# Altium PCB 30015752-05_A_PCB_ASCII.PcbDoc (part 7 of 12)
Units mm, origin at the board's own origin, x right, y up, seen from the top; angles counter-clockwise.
Board outline 100.05 x 72 mm, 10 copper layers (Top, GND_2, Signal_3, Signal_4, PWR_5, GND_6, Signal_7, Signal_8, GND_9, Bottom), stack 1.493 mm thick; 577 components, 546 nets, 2389 pads, 1412 vias.
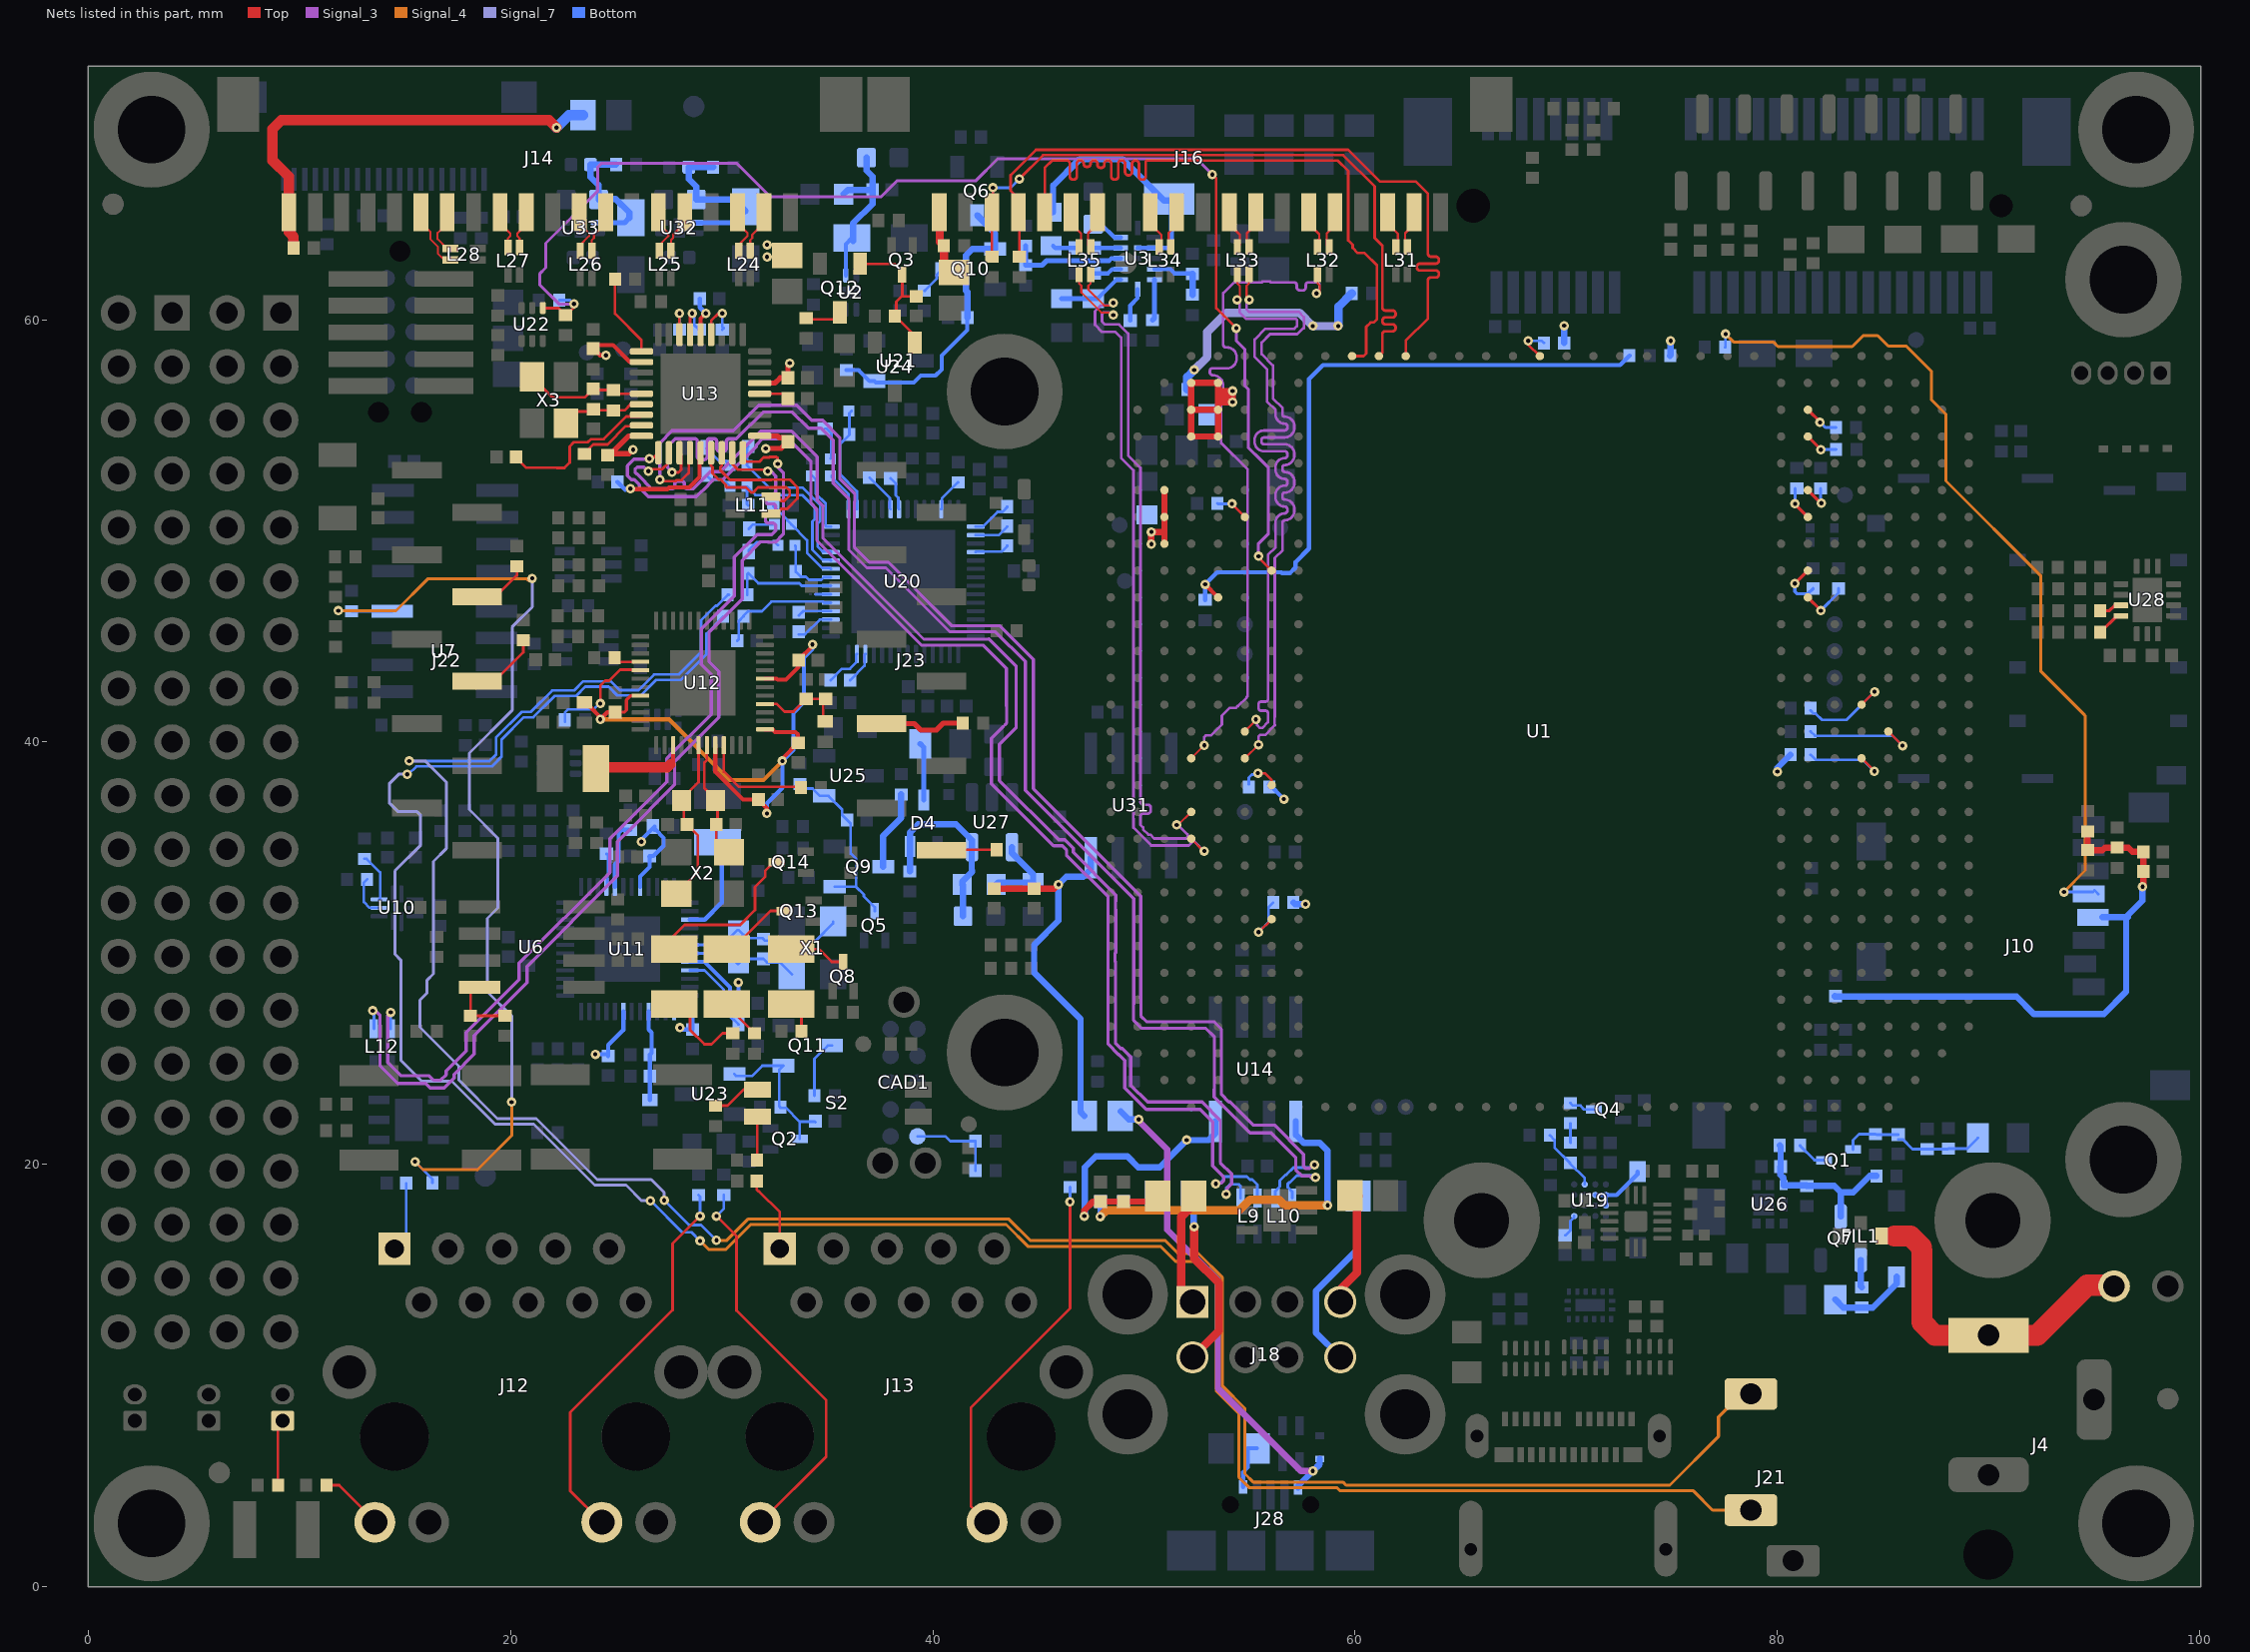
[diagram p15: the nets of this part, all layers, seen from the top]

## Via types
v1: diameter 0.45, hole 0.2, Top to Bottom, tented both sides, 1412 vias

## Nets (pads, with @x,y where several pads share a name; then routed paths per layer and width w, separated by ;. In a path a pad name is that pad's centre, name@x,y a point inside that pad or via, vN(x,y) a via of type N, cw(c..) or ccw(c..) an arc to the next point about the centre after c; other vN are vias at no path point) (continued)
MIPI_DSI1_DATA1_P: L32.4 U1.AK16 | length 32.8
  Top w0.102: U1.AK16@52.24,39.23 52.85,39.84 v1(52.86,39.84) ; v1(58.175,61.25) 58.311,61.25 58.335,61.273 58.335,61.614 58.225,61.724 L32.4@58.225,62.15
  Signal_3 w0.124: v1(52.86,39.84) 52.86,40.237 52.933,40.31 53.173,40.31 53.688,40.825 53.688,41.254 54.05,41.616 54.347,41.616 54.429,41.698 54.457,41.698 54.862,42.103 54.862,42.131 54.91,42.179 54.91,52.917 53.65,54.177 53.65,56.525 53.758,56.633 53.758,56.871 ccw(c53.25,56.871) 53.25,57.378 cw(c53.25,57.508) 53.121,57.508 53.121,57.573 cw(c53.25,57.573) 53.25,57.703 53.932,57.703 ccw(c53.932,58.163) 54.392,58.163 54.392,58.228 ccw(c53.932,58.228) 53.932,58.688 53.887,58.688 cw(c53.887,58.817) 53.758,58.817 53.758,61.258 54.267,61.767 55.581,61.767 55.628,61.814 55.972,61.814 56.019,61.767 57.111,61.767 cw(c57.111,61.64) 57.238,61.64 57.238,61.54 ccw(c57.383,61.54) 57.383,61.395 57.535,61.395 ccw(c57.535,61.522) 57.663,61.522 57.663,61.64 cw(c57.79,61.64) 57.79,61.767 58.244,61.767 58.317,61.694 58.317,61.48 58.175,61.338 v1(58.175,61.25)
MIPI_DSI1_DATA2_N: L33.1 U1.AH16 | length 33
  Top w0.102: U1.AH16@54.78,39.23 v1(55.425,39.875) ; L33.1@54.975,62.15 54.975,61.724 54.865,61.614 54.865,61.073 v1(54.989,60.95)
  Signal_3 w0.124: v1(54.989,60.95) 54.989,60.862 54.865,60.739 54.865,60.485 54.97,60.38 57.337,60.38 57.58,60.137 57.58,59.592 57.531,59.592 57.263,59.324 55.974,59.324 55.575,58.925 55.575,58.375 56.112,57.838 56.112,56.278 56.566,55.825 56.566,55.511 ccw(c56.664,55.511) 56.664,55.413 cw(c56.664,54.953) 57.124,54.953 57.124,54.888 cw(c56.664,54.888) 56.664,54.428 55.695,54.428 ccw(c55.695,54.298) 55.566,54.298 55.566,54.233 ccw(c55.695,54.233) 55.695,54.103 56.664,54.103 cw(c56.664,53.644) 57.124,53.644 57.124,53.578 cw(c56.664,53.578) 56.664,53.119 ccw(c56.664,53.02) 56.566,53.02 56.566,52.892 ccw(c56.664,52.892) 56.664,52.794 cw(c56.664,52.334) 57.124,52.334 57.124,52.269 cw(c56.664,52.269) 56.664,51.809 ccw(c56.664,51.711) 56.566,51.711 56.566,51.583 ccw(c56.664,51.583) 56.664,51.485 cw(c56.664,51.025) 57.124,51.025 57.124,50.96 cw(c56.664,50.96) 56.664,50.5 ccw(c56.664,50.402) 56.566,50.402 56.566,49.08 56.2,48.714 56.2,41.186 56.186,41.172 56.186,40.828 56.2,40.814 56.2,40.798 55.738,40.336 55.498,40.336 55.425,40.263 v1(55.425,39.875)
MIPI_DSI1_DATA2_P: L33.4 U1.AH15 | length 33
  Top w0.102: v1(54.411,60.95) 54.535,61.073 54.535,61.614 54.425,61.724 L33.4@54.425,62.15 ; U1.AH15@54.78,40.5 55.3,41.02 v1(55.3,41.075)
  Signal_3 w0.124: v1(54.411,60.95) 54.411,60.862 54.535,60.739 54.535,60.348 54.833,60.05 57.2,60.05 57.25,60 57.25,59.7 57.125,59.575 55.758,59.575 55.245,59.062 55.245,58.238 55.825,57.658 55.825,56.125 56.235,55.715 56.235,55.511 ccw(c56.664,55.511) 56.664,55.083 cw(c56.664,54.953) 56.793,54.953 56.793,54.888 cw(c56.664,54.888) 56.664,54.758 55.695,54.758 ccw(c55.695,54.298) 55.235,54.298 55.235,54.233 ccw(c55.695,54.233) 55.695,53.773 56.664,53.773 cw(c56.664,53.644) 56.793,53.644 56.793,53.578 cw(c56.664,53.578) 56.664,53.449 ccw(c56.664,53.02) 56.235,53.02 56.235,52.892 ccw(c56.664,52.892) 56.664,52.464 cw(c56.664,52.334) 56.793,52.334 56.793,52.269 cw(c56.664,52.269) 56.664,52.139 ccw(c56.664,51.711) 56.235,51.711 56.235,51.583 ccw(c56.664,51.583) 56.664,51.155 cw(c56.664,51.025) 56.793,51.025 56.793,50.96 cw(c56.664,50.96) 56.664,50.83 ccw(c56.664,50.402) 56.235,50.402 56.235,49.216 55.878,48.859 55.878,42.039 cw(c55.75,42.039) 55.75,41.912 55.552,41.912 ccw(c55.552,41.784) 55.424,41.784 55.424,41.615 ccw(c55.552,41.615) 55.552,41.487 55.75,41.487 cw(c55.75,41.36) 55.878,41.36 55.878,41.275 55.878,40.943 55.601,40.666 55.498,40.666 55.362,40.802 55.362,41.013 v1(55.3,41.075)
MIPI_DSI1_DATA3_N: L35.1 U1.AK19 | length 33.8
  Top w0.102: L35.1@47.475,62.15 47.475,61.724 47.365,61.614 47.365,61.425 48.115,60.675 48.427,60.675 v1(48.55,60.798) ; U1.AK19@52.24,35.42 52.84,34.82 52.85,34.81 52.86,34.82 v1(52.86,34.84)
  Signal_3 w0.124: v1(48.55,60.798) 48.462,60.798 48.339,60.675 47.951,60.675 47.684,60.409 47.684,59.766 48.025,59.425 48.65,59.425 48.92,59.155 48.92,53.455 49.504,52.871 49.504,37.275 49.498,37.268 49.498,37.165 49.495,37.165 49.495,37.127 49.501,37.121 49.501,37.084 49.504,37.08 49.504,37.043 49.504,36.608 49.504,36.571 49.501,36.567 49.501,36.53 49.495,36.524 49.495,36.486 49.498,36.486 49.498,36.383 49.504,36.376 49.504,35.945 50.347,35.102 52.131,35.102 52.3,35.272 52.403,35.272 52.847,34.827 52.85,34.825 52.86,34.835 v1(52.86,34.84)
MIPI_DSI1_DATA3_P: L35.4 U1.AK18 | length 33.9
  Top w0.102: L35.4@46.925,62.15 46.925,61.724 47.035,61.614 47.035,61.288 47.978,60.345 48.427,60.345 v1(48.55,60.221) ; v1(51.553,36.077) 51.627,36.077 U1.AK18@52.24,36.69
  Signal_3 w0.124: v1(48.55,60.221) 48.462,60.221 48.339,60.345 48.088,60.345 48.015,60.272 48.015,59.91 48.15,59.775 48.825,59.775 49.25,59.35 49.25,53.575 49.834,52.991 49.834,37.25 49.834,37.165 ccw(c49.962,37.165) 49.962,37.038 50.185,37.038 cw(c50.185,36.91) 50.312,36.91 50.312,36.741 cw(c50.185,36.741) 50.185,36.613 49.962,36.613 ccw(c49.962,36.486) 49.834,36.486 49.834,36.45 49.834,36.082 49.963,35.953 49.963,35.855 50.206,35.613 50.303,35.613 50.484,35.432 51.994,35.432 52.067,35.505 52.067,35.633 51.62,36.08 51.617,36.077 v1(51.553,36.077)
MIPI_DSI1_I2C0_SCL: J16.17 R182.1 U1.AB1 | length 35.9
  Top w0.127: R182.1@44.1,62.98 44.1,65.05 J16.17@44.05,65.1 44.05,65.75 43.684,66.116 43.684,66.847 44.886,68.048 59.676,68.048 61.175,66.55 62.869,66.55 63.45,65.969 63.45,63.15 63.45,63.134 ccw(c63.597,63.134) 63.597,62.987 63.825,62.987 cw(c63.825,62.839) 63.972,62.839 63.972,62.807 cw(c63.825,62.807) 63.825,62.66 63.45,62.66 63.075,62.66 ccw(c63.075,62.512) 62.928,62.512 62.928,62.48 ccw(c63.075,62.48) 63.075,62.333 63.45,62.333 63.825,62.333 cw(c63.825,62.185) 63.972,62.185 63.972,62.153 cw(c63.825,62.153) 63.825,62.006 63.597,62.006 ccw(c63.597,61.858) 63.45,61.858 63.45,61.8 63.45,60.055 62.4,59.005 U1.AB1@62.4,58.28
MIPI_DSI1_I2C0_SDA: J16.18 R181.1 U1.AC1 | length 32.9
  Top w0.127: R181.1@42.8,62.98 J16.18@42.8,65.1 42.852,65.152 v1(42.852,66.253) ; v1(44.1,66.675) 45.22,67.794 59.443,67.794 60.925,66.313 60.925,63.875 61.295,63.505 61.295,60.6 61.295,60.584 ccw(c61.442,60.584) 61.442,60.437 61.774,60.437 cw(c61.774,60.289) 61.921,60.289 61.921,60.257 cw(c61.774,60.257) 61.774,60.11 61.442,60.11 ccw(c61.442,59.962) 61.295,59.962 61.295,59.93 ccw(c61.442,59.93) 61.442,59.783 61.774,59.783 cw(c61.774,59.635) 61.921,59.635 61.921,59.603 cw(c61.774,59.603) 61.774,59.456 61.43,59.456 ccw(c61.43,59.32) 61.295,59.32 61.295,58.46 ; U1.AC1@61.13,58.28 61.295,58.445
  Bottom w0.127: v1(42.852,66.253) 43.678,66.253 v1(44.1,66.675)
MIPI_DSI1_IRQ_N: R253.2 R254.1 U1.AG9 U22.4 | length 62.6
  Top w0.127: U22.4@21.525,60.555 22.275,60.555 R254.1@22.6,60.23 22.655,60.23 23,60.575 v1(23,60.75) ; v1(53.24,66.88) 53.425,66.695 53.425,60.55 v1(54.375,59.6) ; v1(55.428,48.802) 55.428,48.742 U1.AG9@56.05,48.12
  Signal_3 w0.142: v1(23,60.75) 22.291,60.75 21.375,61.666 21.375,62.171 21.667,62.463 21.667,63.631 24.117,66.081 24.117,67.225 24.292,67.4 30.725,67.4 32.3,65.825 37.55,65.825 38.298,66.573 42.023,66.573 43.075,67.625 52.495,67.625 v1(53.24,66.88) ; v1(54.375,59.6) 54.375,59 54.775,58.6 54.775,56.875 54.95,56.7 54.95,53.93 55.271,53.61 55.29,53.61 55.9,53 55.9,49.872 55.428,49.399 v1(55.428,48.802)
  Bottom w0.127: R253.2@22.305,60.925 22.825,60.925 v1(23,60.75)
MIPI_DSI1_PWM0_OUT: J16.16 U1.AD1 | length 33.8
  Top w0.127: J16.16@45.3,65.1 45.3,67.2 45.641,67.54 46,67.54 46.163,67.54 46.343,67.54 cw(c46.343,67.393) 46.49,67.393 46.49,66.788 ccw(c46.638,66.788) 46.638,66.64 46.67,66.64 ccw(c46.67,66.788) 46.817,66.788 46.817,67.393 cw(c46.965,67.393) 46.965,67.54 46.997,67.54 cw(c46.997,67.393) 47.144,67.393 47.144,67.39 ccw(c47.292,67.39) 47.292,67.243 47.324,67.243 ccw(c47.324,67.39) 47.471,67.39 47.471,67.393 cw(c47.619,67.393) 47.619,67.54 47.651,67.54 cw(c47.651,67.393) 47.798,67.393 47.798,67.344 ccw(c47.946,67.344) 47.946,67.197 47.978,67.197 ccw(c47.978,67.344) 48.125,67.344 48.125,67.393 cw(c48.273,67.393) 48.273,67.54 48.305,67.54 cw(c48.305,67.393) 48.452,67.393 48.452,66.788 ccw(c48.6,66.788) 48.6,66.64 48.632,66.64 ccw(c48.632,66.788) 48.779,66.788 48.779,67.393 cw(c48.927,67.393) 48.927,67.54 48.959,67.54 cw(c48.959,67.393) 49.106,67.393 49.106,66.991 ccw(c49.254,66.991) 49.254,66.844 49.286,66.844 ccw(c49.286,66.991) 49.433,66.991 49.433,67.393 cw(c49.581,67.393) 49.581,67.54 49.613,67.54 cw(c49.613,67.393) 49.76,67.393 49.76,66.788 ccw(c49.908,66.788) 49.908,66.64 49.94,66.64 ccw(c49.94,66.788) 50.087,66.788 50.087,67.479 cw(c50.149,67.479) 50.149,67.54 59.18,67.54 59.675,67.045 59.675,63.762 59.887,63.55 59.887,63.406 60.131,63.163 60.45,63.163 61.041,62.572 61.041,60.028 60.886,59.874 60.734,59.874 60.525,59.665 60.525,58.405 60.4,58.28 U1.AD1@59.86,58.28
NetC5_2: C5.2 D4.2 R26.2 R28.1 U27.5 | length 9
  Bottom w0.3: R28.1@38.91,33.879 38.919,33.888 D4.2@38.919,35.059 38.919,35.719 39.3,36.1 41.1,36.1 41.85,35.35 U27.5@41.85,35.02 41.843,35.013 41.843,33.928 41.85,33.921 41.85,33.85 41.4,33.4 R26.2@41.4,33.25 41.43,33.22 C5.2@41.43,31.75
NetC7_1: C7.1 C8.2 C9.2 R41.1 U2.1 | length 7.8
  Bottom w0.2: U2.1@35.875,62.1 35.875,63.575 C7.1@36.175,63.875
  Bottom w0.3: R41.1@35.775,65.95 35.975,66.15 C9.2@37.14,66.15 ; C7.1@36.225,63.725 36.225,64.575 37.14,65.49 C9.2@37.14,66.15 ; C8.2@36.855,67.675 36.855,67.07 37.14,66.785 C9.2@37.14,66.15
NetC13_1: C13.1 U3.10 | length 1.2
  Bottom w0.2: C13.1@47.66,63.4 U3.10@48.9,63.4
NetC13_2: C13.2 R48.1 | length 1.1
  Bottom w0.2: R48.1@45.7,63.5 45.8,63.4 C13.2@46.74,63.4
NetC14_1: C14.1 U3.8 | length 1.3
  Bottom w0.2: C14.1@47.66,62.2 48.3,62.2 48.5,62.4 U3.8@48.9,62.4
NetC27_2: C27.2 C28.2 J10.4 R53.2 R54.1 R55.2 R56.1 R57.1 | length 26.5
  Top w0.3: R55.2@94.7,35.77 R53.2@94.7,34.88 95.398,34.88 95.518,35 R57.1@96.1,35 96.625,35 96.825,34.8 C28.2@97.34,34.8 C27.2@97.34,33.875 97.34,33.19 v1(97.3,33.15)
  Bottom w0.3: R54.1@82.725,27.97 82.725,27.948 91.327,27.948 92.15,27.125 95.467,27.125 96.525,28.183 96.525,31.625 96.6,31.7 96.519,31.7 ; J10.4@95.4,31.7 96.519,31.7 ; v1(97.3,33.15) 97.3,32.481 96.519,31.7
NetC34_1: C34.1 C112.1 U20.39 | length 7.9
  Bottom w0.127: C112.1@31.26,54 31.2,53.94 C34.1@31.2,53.1 32.247,52.053 33.819,52.053 34.67,51.202 34.67,50.47 34.549,50.35 34.549,49.25 34.763,49.036 35.133,49.036 U20.39@35.17,49
NetC34_2: C34.2 L18.2 | length 1.5
  Bottom w0.127: L18.2@29.305,53.95 29.305,53.885 29.893,53.296 30.204,53.296 C34.2@30.4,53.1
NetC35_1: C35.1 C113.1 U20.38 | length 7.7
  Bottom w0.127: C113.1@31.26,51.2 31.2,51.26 C35.1@31.2,52.1 31.599,51.7 33.812,51.7 34.416,51.097 34.416,50.575 34.295,50.455 34.295,49.104 34.763,48.636 35.133,48.636 U20.38@35.17,48.6
NetC35_2: C35.2 L19.2 | length 1.4
  Bottom w0.127: L19.2@29.305,52.675 29.305,52.61 29.536,52.379 29.574,52.379 29.616,52.421 30.079,52.421 C35.2@30.4,52.1
NetC36_1: C36.1 C114.1 U20.37 | length 4.3
  Bottom w0.127: C114.1@32.44,51.2 32.44,51.19 33.103,50.527 33.103,50.497 C36.1@33.3,50.3 34.041,49.559 34.041,48.958 34.763,48.236 35.133,48.236 U20.37@35.17,48.2
NetC36_2: C36.2 L20.2 | length 1.3
  Bottom w0.127: L20.2@31.28,50.1 31.48,50.3 C36.2@32.5,50.3
NetC41_1: C41.1 Q2.D Q11.G R70.2 U23.G | length 7.4
  Bottom w0.127: U23.G@30.6,24.275 30.691,24.184 31.434,24.184 31.925,24.675 Q11.G@32.925,24.675 32.73,24.48 32.73,22.75 R70.2@32.78,22.7 32.78,22.675 33.04,22.675 33.69,22.025 ; Q2.D@33.69,21.2 33.69,22.025 ; C41.1@34.44,22 34.415,22.025 33.69,22.025
NetC42_2: C42.2 R102.1 U11.7 X1.3 | length 5.4
  Bottom w0.127: U11.7@28.49,29.992 30.258,29.992 30.75,29.5 R102.1@30.8,29.5 31.035,29.735 C42.2@31.975,29.735 32.148,29.562 32.764,29.562 X1.3@33.325,29
NetC43_2: C43.2 R102.2 U11.6 X1.1 | length 7.7
  Bottom w0.127: U11.6@28.49,30.392 30.042,30.392 30.75,31.1 R102.2@30.8,31.1 31.186,30.714 31.926,30.714 C43.2@31.975,30.665 32.043,30.597 34.459,30.597 35.275,31.413 X1.1@35.275,31.5
NetC45_2: C45.2 J12.1 | length 3.3
  Bottom w0.127: J12.1@14.501,16.005 15.06,16.564 C45.2@15.06,19.107
NetC49_2: C49.2 C50.2 L2.2 U11.16 | length 4.3
  Bottom w0.2: U11.16@26.54,27.242 26.54,26.385 26.68,26.245 26.68,25.273 C50.2@26.6,25.192 C49.2@26.6,24.167 L2.2@26.6,23.055
NetC56_2: C56.2 C57.2 C58.2 C59.2 L4.1 U11.8 U11.13 U11.19 U11.44 | length 14.1
  Bottom w0.2: v1(24.01,25.21) 24.55,25.21 C57.2@24.625,25.135 24.625,25.65 25.34,26.365 U11.19@25.34,27.242 ; U11.44@26.14,33.142 26.14,33.64 26.585,34.085 C59.2@26.585,34.5 ; v1(26.2,35.275) 26.2,35.38 26.82,36 26.82,35.85 26.864,35.85 27.252,35.462 27.252,35.088 26.764,34.6 C59.2@26.585,34.6 ; C59.2@26.56,34.575 C59.2@26.61,34.525 ; U11.13@27.74,27.242 28.283,27.242 28.625,26.9 C58.2@28.625,26.385 28.115,26.385 v1(28.025,26.475) ; U11.8@28.49,29.592 29.189,29.592 30.391,28.391 30.391,28.009 30.775,27.625 C56.2@30.79,27.625 v1(30.79,28.615)
NetC60_2: C60.2 R103.1 U12.7 X2.3 | length 5.7
  Top w0.127: U12.7@29.3,39.85 29.3,39.15 29.175,39.025 29.175,37.825 29.8,37.2 29.8,36.16 C60.2@29.74,36.1 29.74,35.385 X2.3@30.35,34.775
NetC61_2: C61.2 R103.2 U12.6 X2.1 | length 8
  Top w0.127: X2.1@27.85,32.825 28.875,33.85 28.875,35.585 C61.2@28.36,36.1 28.2,36.26 28.2,37.4 28.9,38.1 U12.6@28.9,39.85
NetC63_2: C63.2 J13.1 | length 3.7
  Top w0.127: C63.2@31.66,19.2 31.66,18.8 31.745,18.715 31.772,18.715 32.751,17.737 J13.1@32.751,16.005
NetC67_2: C67.2 C68.2 L5.2 U12.16 | length 4.2
  Top w0.127: U12.16@32.05,41.8 32.612,41.8 32.968,41.444 33.407,41.444 34,42.037 C68.2@34,42.04 34.8,42.04 34.8,41.08 L5.2@34.7,40.98
NetC74_2: C74.2 C75.2 C76.2 C77.2 L7.1 U12.8 U12.13 U12.19 U12.44 | length 34.1
  Top w0.15: C77.2@24.95,41.415 25.39,41.415 25.487,41.512 25.487,41.987 25.7,42.2 U12.44@26.15,42.2
  Top w0.2: L7.1@23.5,41.88 23.645,41.88 23.773,41.752 23.773,41.663 24.25,41.186 v1(24.25,41.075) 24.59,41.415 C77.2@24.95,41.415 ; U12.8@29.7,39.85 29.7,38.589 31.014,37.275 C74.2@31.74,37.275 32.133,36.882 32.133,36.627 v1(32.14,36.62) ; U12.13@32.05,40.6 32.4,40.6 32.527,40.473 32.734,40.473 32.738,40.477 33.498,40.477 33.614,40.361 C76.2@33.614,39.96 ; U12.19@32.05,43 32.598,43 32.65,42.948 33.037,42.948 33.64,43.551 C75.2@33.64,43.875 33.64,43.886 34.3,44.546 v1(34.3,44.625) ; v1(32.875,39.1) 32.875,39.221 C76.2@33.614,39.96 ; C76.2@33.625,39.96 C76.2@33.614,39.96
  Signal_4 w0.2: v1(24.25,41.075) 27.503,41.075 30.378,38.2 31.975,38.2 v1(32.875,39.1)
  Bottom w0.2: v1(32.14,36.62) 32.14,37.1 32.875,37.835 v1(32.875,39.1) 33.4,39.625 33.4,41.398 33.412,41.398 33.9,41.886 33.9,44.009 34.3,44.409 v1(34.3,44.625)
NetC79_1: C79.1 C115.1 U20.36 | length 3.1
  Bottom w0.127: C79.1@33.475,49.3 33.51,49.265 C115.1@33.51,48.075 33.51,48.065 33.746,47.828 33.984,47.828 34.128,47.684 34.725,47.684 34.84,47.8 U20.36@35.17,47.8
NetC79_2: C79.2 L21.2 | length 1.7
  Bottom w0.127: L21.2@31.28,49.025 31.28,49.09 31.658,49.468 32.532,49.468 C79.2@32.675,49.325
NetC81_1: C81.1 R135.1 U13.32 X3.3 | length 5.7
  Top w0.127: X3.3@21.019,57.291 21.985,56.325 23.513,56.325 C81.1@23.919,56.731 23.979,56.671 R135.1@24.869,56.671 R135.1@25.04,56.5 ; R135.1@25.14,56.5 U13.32@26.2,56.5
NetC82_1: C82.1 R135.2 U13.33 X3.1 | length 4
  Top w0.127: X3.1@22.619,55.091 23.179,55.651 23.919,55.651 23.979,55.711 R135.2@24.869,55.711 25.411,55.711 25.7,56 U13.33@26.2,56
NetC85_2: C85.2 C86.2 L29.2 U14.5 | length 19.8
  Signal_4 w0.4: v1(47.925,17.525) 48.225,17.825 54.527,17.825 55.027,18.325 56.4,18.325 56.665,18.06 v1(58.7,18.06)
  Bottom w0.3: v1(47.925,17.525) 47.95,17.55 C85.2@47.95,18.24 C86.2@49.025,18.24 50.39,18.24 L29.2@50.65,18.5 ; U14.5@57.195,22.03 57.195,21.399 57.569,21.025 58.325,21.025 58.7,20.65 v1(58.7,18.06)
NetC87_2: C87.2 C88.2 L30.2 U14.8 | length 14.3
  Top w0.3: v1(47.175,17.55) 47.175,17.825 47.59,18.24 C87.2@47.95,18.24 C88.2@49.025,18.24 50.65,18.24 L30.2@50.65,18.5
  Bottom w0.3: v1(47.175,17.55) 47.2,17.575 47.2,19.856 47.721,20.377 49.221,20.377 49.732,19.866 50.741,19.866 v1(52.025,21.15) 53.075,21.15 53.385,21.46 U14.8@53.385,22.03
NetC89_1: C89.1 Q3.D Q12.G R145.2 U24.G | length 6.9
  Top w0.127: Q12.G@36.55,62.65 38.175,62.65 38.55,62.275 Q3.D@38.55,62.135 38.55,61.135 38.525,61.11 ; U24.G@39.225,59 U24.G@39.15,58.925 39.15,59.242 38.217,60.175 R145.2@38.205,60.175 38.271,60.241 38.271,60.855 38.525,61.11 ; C89.1@39.225,61.11 38.525,61.11
NetC90_2: C90.2 C91.2 C92.2 C93.2 C94.2 C95.2 L15.1 U13.5 U13.10 U13.15 U13.23 U13.29 U13.36 | length 18.8
  Top w0.2: v1(24.52,58.32) 24.23,58.32 C94.2@23.919,58.631 24.088,58.8 24.764,58.8 24.765,58.799 24.851,58.799 25.65,58 U13.29@26.2,58 ; v1(25.676,52.003) 25.657,52.003 25.627,51.973 27.423,51.973 27.514,52.064 28.464,52.064 28.95,52.55 28.95,53.65 U13.5@29,53.7 ; U13.23@29,59.3 29,60.05 v1(29.25,60.3)
  Top w0.25: C90.2@24.6,53.66 C90.2@24.76,53.66 ; v1(25.8,53.85) 25.61,53.66 C90.2@24.76,53.66 ; U13.36@26.2,54.5 25.6,54.5 C90.2@24.76,53.66 ; U13.10@31.8,54.5 32.641,54.5 32.731,54.41 32.955,54.41 C92.2@33.14,54.225 32.815,53.9 v1(32.08,53.9) ; U13.15@31.8,57 32.525,57 32.775,57.25 C93.2@33.14,57.25 33.14,57.865 v1(33.22,57.945)
  Bottom w0.2: C91.2@25.06,52.325 25.433,51.952 25.484,52.003 v1(25.676,52.003) ; C95.2@28.965,61 28.965,60.585 v1(29.25,60.3)
  other v1: 32.15,62.975 32.15,63.55
NetC96_2: C96.2 U13.14 | length 1.4
  Top w0.127: U13.14@31.8,56.5 32.915,56.5 C96.2@33.14,56.275
NetC97_2: C97.2 U13.34 | length 7.7
  Top w0.127: C97.2@20.26,53.5 20.26,53.472 20.74,52.992 22.195,52.992 22.203,52.984 22.547,52.984 22.8,53.237 22.8,54 23,54.2 23.661,54.2 23.81,54.35 24.412,54.35 25.483,55.421 26.121,55.421 U13.34@26.2,55.5
NetC108_2: C108.2 U19.D4 | length 1.1
  Bottom w0.127: C108.2@69.95,16.635 69.96,16.635 70.196,16.871 70.196,17.32 70.38,17.503 U19.D4@70.38,17.55
NetC109_1: C109.1 R159.2 U20.44 | length 5.2
  Bottom w0.127: C109.1@36.15,55.675 36.045,55.57 R159.2@36.045,54.575 36.045,54.55 35.609,54.114 35.609,52.667 36.4,51.876 U20.44@36.4,51.03
NetC110_1: C110.1 U20.42 | length 2.9
  Bottom w0.127: C110.1@34.3,52.6 34.446,52.454 34.446,51.785 34.924,51.308 34.924,50.236 34.96,50.2 U20.42@35.17,50.2
NetC111_1: C111.1 U20.43 | length 1.9
  Bottom w0.127: C111.1@35.2,52.6 35.2,52.55 36,51.75 U20.43@36,51.03
NetC111_2: C111.2 L17.2 | length 1.6
  Bottom w0.127: L17.2@34.9,54.845 34.965,54.845 35.196,54.614 35.196,53.465 C111.2@35.165,53.435
NetC116_1: C116.1 R164.1 U20.35 | length 5.2
  Bottom w0.127: R164.1@31.205,46.975 31.205,47.945 C116.1@31.26,48 31.26,47.99 31.735,47.516 33.672,47.516 33.788,47.4 U20.35@35.17,47.4
NetC117_1: C117.1 R165.1 U20.33 | length 5.7
  Bottom w0.127: C117.1@30.74,44.8 30.809,44.868 30.809,45.729 R165.1@31.03,45.95 31.03,45.975 31.251,46.196 31.899,46.196 32.353,46.65 34.789,46.65 34.84,46.6 U20.33@35.17,46.6
NetC127_1: C127.1 U20.27 | length 2
  Bottom w0.127: C127.1@35.165,42.925 35.165,42.935 35.697,43.467 36.068,43.467 36.363,43.763 36.363,44.133 U20.27@36.4,44.17
NetC127_2: C127.2 U20.26 | length 1.5
  Bottom w0.127: C127.2@36.085,42.925 36.085,42.935 36.764,43.613 36.764,44.133 U20.26@36.8,44.17
NetC128_2: C128.2 U20.32 | length 1.6
  Bottom w0.127: C128.2@33.66,46 33.86,46.2 U20.32@35.17,46.2
NetC129_2: C129.2 U20.31 | length 1.8
  Bottom w0.127: C129.2@33.66,45.1 33.95,45.1 34.65,45.8 U20.31@35.17,45.8
NetC130_1: C130.1 U20.48 | length 1.9
  Bottom w0.127: C130.1@37,52.515 37.01,52.515 37.964,51.561 37.964,51.066 U20.48@38,51.03
NetC131_2: C131.2 U20.49 | length 1.6
  Bottom w0.127: C131.2@38,52.49 38.01,52.49 38.246,52.254 38.246,51.691 38.363,51.574 38.363,51.066 U20.49@38.4,51.03
NetC132_2: C132.2 Q1.G R25.2 R64.1 R162.1 R255.1 | length 6.8
  Bottom w0.127: Q1.G@83.59,20.7 83.59,21.14 83.88,21.43 R25.2@84.65,21.43 ; R25.2@84.695,21.41 C132.2@85.725,21.41 ; C132.2@85.725,21.185 85.94,21.185 86.405,20.72 R64.1@87.1,20.72 88.075,20.72 R162.1@88.1,20.745 88.995,20.745 R255.1@89.5,21.25
NetC133_1: C133.1 Q6.D Q10.G R193.2 U21.G | length 14.4
  Bottom w0.2: R193.2@35.9,57.62 36.48,57.62 37,57.1 U21.G@37.225,57.1 37.302,57.023 39.098,57.023 39.427,57.352 40.127,57.352 40.423,57.648 40.423,58.298 41.635,59.51 C133.1@41.635,60.1
  Bottom w0.3: C133.1@41.635,60.1 41.635,61.315 41.575,61.375 41.575,63.05 41.875,63.35 Q10.G@42.95,63.35 42.95,64.1 Q6.D@42.1,64.95
NetC134_1: C134.1 Q5.D Q9.G R169.2 U25.G | length 9
  Bottom w0.127: R169.2@33.7,38.02 33.921,37.799 34.301,37.799 34.65,37.45 U25.G@34.85,37.45 35.05,37.45 35.704,36.796 35.704,36.537 C134.1@35.94,36.3 36.109,36.131 36.109,34.727 36.36,34.476 36.36,33.15 ; Q9.G@35.35,33.15 36.36,33.15 ; Q5.D@37.25,31.99 37.25,32.175 36.737,32.688 36.737,32.773 36.36,33.15
NetC135_2: C135.2 U3.11 | length 1.6
  Bottom w0.2: C135.2@47.6,64.53 47.97,64.53 48.6,63.9 U3.11@48.9,63.9
NetC136_2: C136.2 U3.6 | length 1.6
  Bottom w0.2: C136.2@49.35,59.96 49.35,60.675 49.7,61.025 U3.6@49.7,61.45
NetC142_1: C142.1 Q7.3 R21.1 R23.1 R24.2 U26.3 | length 8
  Bottom w0.3: R23.1@80.12,20.9 80.16,20.86 C142.1@80.16,19.9 80.15,19.89 80.15,19.5 80.3,19.35 U26.3@80.3,19.01 81.37,19.01 R21.1@81.4,18.98 82.695,18.98 83,18.675 ; Q7.3@83,17.53 83,18.675 ; R24.2@84.695,19.45 84.375,19.45 83.6,18.675 83,18.675
NetC148_2: C148.2 C149.2 L37.2 U31.8 | length 17.9
  Top w0.3: C149.2@42.9,33.06 C148.2@44.8,33.06 45.76,33.06 v1(45.952,33.252)
  Bottom w0.3: v1(45.952,33.252) 45.952,31.536 44.798,30.381 44.798,29.077 47,26.875 47,22.475 L37.2@47.175,22.3 ; v1(45.952,33.252) 46.325,33.625 47.125,33.625 47.485,33.985 U31.8@47.485,34.53
NetC155_1: C155.1 C156.2 C157.2 R2.2 U32.1 | length 7.9
  Bottom w0.25: U32.1@28.81,64.6 30.575,64.6 C155.1@31.125,65.15
  Bottom w0.3: R2.2@29.595,67.225 C157.2@28.435,67.225 28.435,66.665 28.795,66.305 C156.2@28.795,65.7 30.575,65.7 C155.1@31.125,65.15
NetC159_1: C159.1 C160.2 C161.2 R3.2 U33.1 | length 6.5
  Bottom w0.25: U33.1@24.21,64.6 25.4,64.6 C159.1@25.625,64.825
  Bottom w0.3: R3.2@24.995,67.35 C161.2@23.785,67.35 23.785,66.765 24.17,66.38 C160.2@24.17,65.7 24.195,65.725 24.975,65.725 25.625,65.075 C159.1@25.625,64.825
NetCAD1_5: CAD1.5 R14.2 R29.2 | length 4.2
  Bottom w0.127: CAD1.5@39.27,21.33 40.595,21.33 40.825,21.1 R29.2@42.02,21.1 R14.2@42.02,19.7
NetD2_2: D2.2 J28.1 L37.1 | length 23.2
  Signal_3 w0.3: v1(49.75,22.125) 49.75,22.06 51.1,20.71 51.1,16.9 53.5,14.5 53.5,9.4 57.425,5.475 v1(58,5.475)
  Bottom w0.3: L37.1@48.9,22.5 49.275,22.125 v1(49.75,22.125) ; J28.1@57.3,4.7 57.3,4.775 v1(58,5.475) 58.325,5.8 D2.2@58.325,6.05
NetD3_K: D3.K R19.1 R20.1 | length 3.9
  Bottom w0.3: R19.1@82.75,13.6 83.13,13.22 R20.1@84,13.22 84.52,13.22 85.65,14.35 D3.K@85.65,14.675
NetD4_3: D4.3 R31.1 | length 2.7
  Bottom w0.25: R31.1@39.4,39.92 39.569,39.751 D4.3@39.569,37.259
NetD5_A: D5.A R42.1 | length 1.5
  Top w0.127: D5.A@33.3,27.6 33.78,27.12 R42.1@33.78,26.3
NetD5_K: D5.K Q8.D | length 2.7
  Top w0.127: D5.K@33.3,30.2 34.6,30.2 35.21,29.59 Q8.D@35.75,29.59
NetD8_A: D8.A U19.B1 U19.B2 U19.C1 | length 3
  Bottom w0.2: U19.B2@71.38,18.55 U19.B1@71.88,18.55 ; U19.C1@71.88,18.05 U19.B1@71.88,18.55 ; D8.A@73.38,19.65 73.38,19.541 72.389,18.55 U19.B1@71.88,18.55
NetD11_A: D11.A R203.1 | length 2
  Top w0.127: D11.A@30.1,27.6 30.155,27.6 R203.1@31.55,26.205
NetD11_K: D11.K Q13.D | length 3.6
  Top w0.127: D11.K@30.1,30.2 D11.K@30.25,30.2 30.52,30.2 32.32,32 Q13.D@32.97,32
NetD12_A: D12.A R204.1 | length 4.7
  Top w0.127: D12.A@27.6,27.6 D12.A@27.75,27.6 28.5,27.6 28.5,26.362 29.178,25.685 29.522,25.685 30.043,26.205 R204.1@30.525,26.205
NetD12_K: D12.K Q14.D | length 7.8
  Top w0.127: D12.K@27.6,30.2 27.6,30.7 28.24,31.34 30.88,31.34 31.58,32.04 31.58,33.14 32.06,33.62 32.06,33.9 32.46,34.3 Q14.D@32.61,34.3
NetFIL1_1: FIL1.1 J4.1 J5.1 | length 15.4
  Top w1: 85.55,16.6 86.3,16.6 86.823,16.077 86.823,15.951 86.85,15.924 86.85,12.525 87.471,11.904 J4.1@90,11.904 92.304,11.904 94.675,14.275 J5.1@95.955,14.275
NetJ6_1: J6.1 R18.2 | length 3.1
  Top w0.127: R18.2@8.98,4.8 8.98,7.63 J6.1@9.2,7.85
NetJ10_5: J10.5 R58.2 | length 41.4
  Signal_4 w0.142: v1(77.55,59.325) 77.925,58.95 79.812,58.95 80.029,58.733 83.55,58.733 84.068,59.251 84.754,59.251 85.255,58.75 86.11,58.75 87.292,57.568 87.292,56.224 87.989,55.527 87.989,52.37 92.469,47.89 92.469,43.365 94.544,41.29 94.59,41.245 94.59,33.915 v1(93.575,32.9)
  Bottom w0.127: R58.2@77.53,58.7 77.55,58.72 v1(77.55,59.325) ; v1(93.575,32.9) 94.95,32.9 95.025,32.975 J10.5@95.2,32.8
NetJ12_D1: J12.D1 R84.1 | length 3
  Top w0.127: R84.1@11.28,4.8 11.88,4.8 13.571,3.109 J12.D1@13.571,3.051
NetJ12_D3: J12.D3 R83.1 | length 18.7
  Top w0.127: J12.D3@24.305,3.051 22.825,4.531 22.825,8.25 27.675,13.1 27.675,16.25 v1(28.975,17.55)
  Bottom w0.127: R83.1@28.9,18.545 28.98,18.465 28.975,18.46 v1(28.975,17.55)
NetJ13_D1: J13.D1 R116.1 | length 19.1
  Top w0.127: v1(29.75,17.55) 30.7,16.6 30.7,13.075 34.95,8.825 34.95,6.165 J13.D1@31.836,3.051
  Bottom w0.127: v1(29.75,17.55) 30.1,17.9 R116.1@30.1,18.545
NetJ13_D3: J13.D3 R115.1 | length 18.1
  Top w0.127: J13.D3@42.571,3.051 42.555,3.051 41.8,3.806 41.8,8.475 46.5,13.175 v1(46.5,18.225)
  Bottom w0.127: v1(46.5,18.225) R115.1@46.5,18.92
NetJ14_2: J14.2 L24.2 | length 2.1
  Top w0.102: L24.2@31.35,63.275 31.35,63.775 31.45,63.875 31.45,64.025 32,64.575 J14.2@32,65.1
NetJ14_3: J14.3 L24.3 | length 2.2
  Top w0.102: J14.3@30.75,65.1 30.75,64.575 31.22,64.105 31.22,63.97 30.8,63.55 L24.3@30.8,63.275
NetJ14_5: J14.5 L25.2 | length 2.1
  Top w0.102: L25.2@27.6,63.275 27.6,63.775 27.7,63.875 27.7,64.025 28.25,64.575 J14.5@28.25,65.1
NetJ14_6: J14.6 L25.3 | length 2.2
  Top w0.102: J14.6@27,65.1 27,64.575 27.47,64.105 27.47,63.97 27.05,63.55 L25.3@27.05,63.275
NetJ14_8: J14.8 L26.2 | length 2.1
  Top w0.102: L26.2@23.85,63.275 23.85,63.775 23.95,63.875 23.95,64.025 24.5,64.575 J14.8@24.5,65.1
NetJ14_9: J14.9 L26.3 | length 2.2
  Top w0.102: J14.9@23.25,65.1 23.25,64.575 23.72,64.105 23.72,63.97 23.3,63.55 L26.3@23.3,63.275
NetJ14_11: J14.11 L27.2 | length 1.9
  Top w0.102: L27.2@20.425,63.425 20.425,63.851 20.315,63.961 20.315,64.09 20.75,64.525 J14.11@20.75,65.1
NetJ14_12: J14.12 L27.3 | length 1.9
  Top w0.102: J14.12@19.5,65.1 19.5,64.575 19.985,64.09 19.985,63.961 19.875,63.851 L27.3@19.875,63.425
NetJ14_14: J14.14 L28.2 | length 2.3
  Top w0.102: J14.14@17,65.1 17,64.575 16.54,64.115 16.54,63.822 16.987,63.375 L28.2@17.15,63.375
NetJ14_15: J14.15 L28.3 | length 3
  Top w0.102: J14.15@15.75,65.1 15.75,64.625 16.21,64.165 16.21,63.81 16.553,63.467 16.553,63.147 16.875,62.825 L28.3@17.15,62.825
NetJ14_20: J14.20 L8.2 R134.2 | length 21.3
  Top w0.5: R134.2@9.72,63.4 9.72,63.93 9.5,64.15 J14.20@9.5,65.1 9.5,66.775 8.725,67.55 8.725,69.025 9.15,69.45 21.825,69.45 v1(22.175,69.1)
  Bottom w0.5: v1(22.175,69.1) 22.775,69.7 L8.2@23.425,69.7
NetJ16_2: J16.2 L31.2 | length 1.9
  Top w0.102: L31.2@62.475,63.45 62.375,63.55 62.375,64.1 62.8,64.525 J16.2@62.8,65.1
NetJ16_3: J16.3 L31.3 | length 1.9
  Top w0.102: J16.3@61.55,65.1 61.55,64.55 62.025,64.075 62.025,63.55 L31.3@61.925,63.45
NetJ16_5: J16.5 L32.2 | length 1.9
  Top w0.102: L32.2@58.775,63.45 58.65,63.575 58.65,64.075 59.05,64.475 J16.5@59.05,65.1
NetJ16_6: J16.6 L32.3 | length 1.9
  Top w0.102: J16.6@57.8,65.1 57.8,64.55 58.3,64.05 58.3,63.825 58.225,63.75 L32.3@58.225,63.45
NetJ16_8: J16.8 L33.2 | length 1.9
  Top w0.102: L33.2@54.975,63.45 54.875,63.55 54.875,64.1 55.3,64.525 J16.8@55.3,65.1
NetJ16_9: J16.9 L33.3 | length 1.9
  Top w0.102: J16.9@54.05,65.1 54.05,64.525 54.545,64.03 54.545,63.57 L33.3@54.425,63.45
NetJ16_11: J16.11 L34.2 | length 1.8
  Top w0.102: L34.2@51.275,63.45 51.175,63.55 51.175,64.125 51.55,64.5 J16.11@51.55,65.1
NetJ16_12: J16.12 L34.3 | length 1.9
  Top w0.102: J16.12@50.3,65.1 50.3,64.556 50.825,64.031 50.825,63.55 L34.3@50.725,63.45
NetJ16_14: J16.14 L35.2 | length 1.9
  Top w0.102: L35.2@47.475,63.45 47.35,63.575 47.35,64.1 47.8,64.55 J16.14@47.8,65.1
NetJ16_15: J16.15 L35.3 | length 1.9
  Top w0.102: J16.15@46.55,65.1 46.55,64.55 47.02,64.08 47.02,63.795 46.925,63.7 L35.3@46.925,63.45
NetJ16_20: J16.20 L36.2 R215.2 | length 3.1
  Top w0.4: J16.20@40.3,65.1 40.327,65.073 40.327,63.693 R215.2@40.52,63.5 40.52,62.73 L36.2@41,62.25
NetJ18_A1: J18.A1 L30.1 | length 5.5
  Top w0.4: J18.A1@52.301,13.485 51.768,14.018 51.768,17.518 52.198,17.948 52.198,18.348 L30.1@52.35,18.5
NetJ18_A4: J18.A4 L14.2 | length 5.4
  Top w0.4: J18.A4@59.301,13.485 59.301,14.076 60.098,14.873 60.098,18.448 L14.2@60.15,18.5
NetJ18_B1: J18.B1 L29.1 | length 8.6
  Top w0.4: J18.B1@52.301,10.865 53.55,12.114 53.55,14.375 52.375,15.55 v1(52.375,17.05)
  Bottom w0.3: L29.1@52.35,18.5 52.35,17.075 v1(52.375,17.05)
NetJ18_B4: J18.B4 L13.2 | length 8.9
  Bottom w0.3: J18.B4@59.301,10.865 58.15,12.016 58.15,14.006 60.123,15.979 60.123,18.473 L13.2@60.15,18.5
NetJ21_2: J21.2 R165.2 | length 113.9
  Signal_4 w0.142: v1(28.975,16.375) 29.373,15.977 30.202,15.977 31.375,17.15 43.473,17.15 44.525,16.098 50.802,16.098 51.5,15.4 52.5,15.4 53.425,14.475 53.425,9.275 54.5,8.2 54.5,5.175 55,4.675 59.15,4.675 59.292,4.533 76.025,4.533 76.933,3.625 J21.2@78.75,3.625
  Signal_7 w0.142: v1(15.1,38.475) 14.7,38.475 14.275,38.05 14.275,37.1 14.675,36.7 15.576,36.7 15.738,36.538 15.738,35.113 14.528,33.903 14.528,29.951 14.802,29.677 14.802,24.927 15.789,23.94 17.225,23.94 19.265,21.9 21.101,21.9 23.988,19.013 25.471,19.013 26.21,18.275 ; v1(26.626,18.276) 26.211,18.276 ; 26.21,18.275 26.211,18.276
  Bottom w0.127: v1(15.1,38.475) 15.163,38.475 15.534,38.846 19.105,38.846 19.573,39.313 19.573,40.12 20.628,41.176 21.072,41.176 22.082,42.185 23.107,42.185 23.543,42.621 24.644,42.621 25.06,42.205 26.165,42.205 26.906,42.947 28.068,42.947 29.279,44.158 29.279,45.134 30.07,45.925 R165.2@30.07,45.95 ; v1(26.626,18.276) 28.119,16.783 28.566,16.783 v1(28.975,16.375)
NetJ21_3: J21.3 R164.2 | length 115.6
  Signal_4 w0.142: v1(29.75,16.4) 30.244,16.4 31.263,17.419 43.584,17.419 44.604,16.4 51,16.4 51.625,15.775 52.575,15.775 53.725,14.625 53.725,9.5 54.776,8.449 54.776,5.351 55.175,4.952 59.423,4.952 59.573,4.802 74.902,4.802 77.212,7.113 77.212,8.037 78.3,9.125 J21.3@78.75,9.125 ; J21.3@78.85,9.025 78.925,9.1 J21.3@79.4,9.1
  Signal_7 w0.142: v1(15.2,39.1) 15.956,39.1 16.949,38.107 16.949,34.95 16.349,34.35 16.349,29.024 16.049,28.724 16.049,28.126 15.702,27.779 15.702,26.496 17.549,24.649 17.549,23.997 19.376,22.169 21.213,22.169 24.099,19.283 26.667,19.283 27.275,18.675 v1(27.275,18.3)
  Bottom w0.127: v1(15.2,39.1) 19,39.1 19.319,39.419 19.319,40.225 20.523,41.43 20.967,41.43 21.977,42.439 23.002,42.439 23.438,42.875 24.749,42.875 25.165,42.459 26.059,42.459 26.801,43.201 27.963,43.201 29.025,44.263 29.025,45.77 29.706,46.45 29.771,46.45 30.295,46.975 R164.2@30.345,46.975 ; v1(27.275,18.3) 28.45,17.125 29.025,17.125 v1(29.75,16.4)
NetJ22_4: J22.4 R189.2 | length 2.7
  Top w0.127: J22.4@18.417,46.875 19.275,46.875 20.3,47.9 R189.2@20.3,48.32
NetJ22_6: J22.6 R190.2 | length 3.3
  Top w0.127: J22.6@18.417,42.875 19.225,42.875 20.6,44.25 R190.2@20.6,44.82
NetJ23_7: J23.7 R196.1 | length 4.1
  Top w0.25: J23.7@37.567,40.875 39.125,40.875 39.432,40.568 40.168,40.568 40.5,40.9 R196.1@41.42,40.9
NetJ23_10: J23.10 R197.1 | length 2.6
  Top w0.127: J23.10@40.417,34.875 40.442,34.9 R197.1@43.02,34.9
NetJ28_5: J28.5 L39.2 | length 2.3
  Bottom w0.2: J28.5@54.7,4.725 54.7,5.425 54.925,5.65 54.925,6.55 L39.2@55.35,6.55
NetL1_1: L1.1 R48.2 U3.2 U3.13 | length 11.9
  Bottom w0.2: U3.13@49.7,63.4 U3.2@50.5,63.4 51.2,63.4
  Bottom w0.25: 51.2,63.4 51.3,63.5 51.3,65.55 L1.1@51.2,65.65
  Bottom w0.3: R48.2@45.7,65.1 45.7,66.351 46.949,67.6 49,67.6 50.95,65.65 L1.1@51.2,65.65
NetL3_1: L3.1 U11.3 | length 4.8
  Bottom w0.2: U11.3@28.49,31.592 29.199,31.592 30,32.393 30,35.152 L3.1@30.14,35.292
NetL6_1: L6.1 U12.3 | length 4.4
  Top w0.2: 27.575,38.95 27.7,39.075 U12.3@27.7,39.85
  Top w0.5: L6.1@24.2,38.7 24.299,38.799 27.424,38.799 27.575,38.95
NetL9_1: L9.1 U13.1 | length 62.6
  Top w0.132: v1(26.575,53.425) 26.636,53.486 26.786,53.486 U13.1@27,53.7
  Signal_3 w0.142: 34.505,50.955 34.505,49.545 39.475,44.575 42.4,44.575 ; 43.312,40.712 43.491,40.891 43.491,41.7
  Signal_3 w0.157: v1(26.575,53.425) 26.516,53.425 26.481,53.39 26.478,53.393 25.847,53.393 25.532,53.078 25.532,52.622 25.721,52.433 25.855,52.433 26.107,52.181 26.107,52.047 26.528,51.626 28.806,51.626 29.357,52.177 29.357,52.184 29.614,52.44 30.084,52.44 31.649,54.005 31.649,54.078 31.93,54.359 33.152,54.359 34.228,53.283 34.228,51.306 34.505,51.029 34.505,50.955 ; 42.4,44.575 43.491,43.484 43.491,41.7 ; 43.312,40.712 42.775,40.175 42.775,38.025 45.718,35.082 46.14,35.082 46.333,34.89 46.333,34.642 48.3,32.675 48.3,25.689 48.784,25.205 48.804,25.205 49.093,24.916 49.093,23.626 50.116,22.603 52.656,22.603 53.252,22.007 53.252,19.927 53.782,19.397 53.782,19.228 53.683,19.129 53.458,19.129 v1(53.402,19.073)
  Bottom w0.132: v1(53.402,19.073) 53.577,19.073 53.75,19.246 53.75,19.375 53.793,19.418 54.878,19.418 55.012,19.284 55.139,19.284 55.375,19.048 L9.1@55.375,18.4
NetL9_4: L9.4 U13.2 | length 62.7
  Top w0.132: v1(26.525,52.825) 26.525,52.875 26.475,52.925 27.175,52.925 27.5,53.25 U13.2@27.5,53.7
  Signal_3 w0.142: 34.803,51.178 34.803,49.647 39.575,44.875 42.65,44.875
  Signal_3 w0.157: v1(26.525,52.825) 26.325,53.025 26,53.025 25.9,52.925 25.9,52.775 25.957,52.718 25.973,52.718 26.391,52.299 26.391,52.284 26.681,51.994 27.55,51.994 27.641,51.994 ccw(c27.641,52.132) 27.779,52.132 27.779,52.211 cw(c27.916,52.211) 27.916,52.349 28.099,52.349 cw(c28.099,52.211) 28.236,52.211 28.236,52.132 ccw(c28.373,52.132) 28.373,51.994 28.6,51.994 28.653,51.994 29.467,52.808 29.932,52.808 31.851,54.727 33.304,54.727 34.525,53.506 34.525,51.456 34.803,51.178 ; 42.65,44.875 43.95,43.575 43.95,40.7 43.15,39.9 43.15,38.175 45.958,35.367 46.258,35.367 46.647,34.978 46.647,34.781 48.668,32.76 48.668,32.467 48.649,32.448 48.649,32.092 48.668,32.073 48.668,30.017 48.629,29.978 48.629,29.622 48.649,29.602 48.649,25.742 48.902,25.489 48.975,25.489 49.377,25.087 49.377,24.8 49.377,23.744 50.172,22.949 52.757,22.949 53.62,22.086 53.62,20.08 54.15,19.55 54.15,19.075 53.944,18.869 53.944,18.643 v1(53.888,18.587)
  Bottom w0.132: v1(53.888,18.587) 53.888,18.863 54.075,19.05 54.5,19.05 54.575,18.975 L9.4@54.575,18.4
NetL10_1: L10.1 U13.3 | length 65.7
  Top w0.132: v1(27.65,52.775) 27.95,52.775 28.075,52.9 28.075,53.625 U13.3@28,53.7
  Signal_3 w0.142: 36.025,51.514 36.025,49.1 36.875,48.25 37.775,48.25 40.801,45.224 42.976,45.224 ; 49.511,27.6 49.511,26.814 49.875,26.45 52.925,26.45 53.325,26.05 53.325,23.555
  Signal_3 w0.157: v1(27.65,52.775) 27.65,52.798 27.434,53.014 27.434,54.009 27.798,54.373 28.275,54.373 28.712,54.373 cw(c28.712,54.236) 28.849,54.236 28.849,53.515 ccw(c28.986,53.515) 28.986,53.377 29.169,53.377 ccw(c29.169,53.515) 29.306,53.515 29.306,54.236 cw(c29.444,54.236) 29.444,54.373 29.627,54.373 cw(c29.627,54.236) 29.764,54.236 29.764,53.912 ccw(c29.901,53.912) 29.901,53.774 30.084,53.774 ccw(c30.084,53.912) 30.221,53.912 30.221,54.236 cw(c30.359,54.236) 30.359,54.373 30.45,54.373 30.701,54.373 31.959,55.631 33.348,55.631 34.11,54.869 34.7,54.869 35.278,54.291 35.278,52.261 36.025,51.514 ; 42.976,45.224 44.388,43.812 44.388,37.712 49.511,32.589 49.511,27.6 ; 53.325,23.555 53.325,23.187 55.021,21.491 56.029,21.491 57.191,20.329 57.191,19.751 57.492,19.45 57.836,19.45 57.996,19.291 58.084,19.379 58.125,19.379 v1(58.128,19.376)
  Bottom w0.132: L10.1@57.025,18.4 57.025,18.7 56.809,18.916 56.809,19.084 56.864,19.139 56.901,19.139 57.237,19.475 58.029,19.475 v1(58.128,19.376)
NetL10_4: L10.4 U13.4 | length 65.6
  Top w0.132: v1(27.075,52.425) 27.143,52.357 27.823,52.357 27.873,52.407 28.103,52.407 28.318,52.622 28.443,52.747 28.443,53.643 U13.4@28.5,53.7
  Signal_3 w0.142: 36.28,51.78 36.302,51.758 36.302,51.399 36.294,51.392 36.294,49.212 36.987,48.519 37.887,48.519 40.905,45.501 43.174,45.501 ; 49.848,27.875 49.848,27.027 50.125,26.75 53.325,26.75 53.668,26.407 53.668,23.733
  Signal_3 w0.157: v1(27.075,52.425) 27.066,52.434 27.066,54.162 27.645,54.741 30.549,54.741 31.754,55.947 33.553,55.947 34.263,55.237 34.779,55.237 35.594,54.422 35.594,52.466 36.28,51.78 ; 43.174,45.501 44.756,43.919 44.756,37.794 49.848,32.702 49.848,27.875 ; 53.668,23.733 53.668,23.303 54.022,22.949 54.083,22.949 55.174,21.859 56.182,21.859 57.559,20.482 57.559,19.903 57.644,19.818 57.836,19.818 57.996,19.978 v1(58.075,19.978)
  Bottom w0.132: L10.4@56.225,18.4 56.225,18.725 56.441,18.941 56.441,19.237 56.711,19.507 56.748,19.507 57.084,19.843 57.94,19.843 v1(58.075,19.978)
NetL11_1: L11.1 U13.6 | length 6.6
  Top w0.132: U13.6@29.5,53.7 29.5,53.084 29.566,53.018 29.566,52.722 29.865,52.423 29.961,52.423 30.206,52.178 30.206,52.082 30.232,52.057 31.15,52.057 31.382,51.825 31.493,51.825 31.725,52.057 33.072,52.057 33.225,51.904 33.225,51.684 32.95,51.409 32.841,51.409 32.625,51.625 L11.1@32.325,51.625
NetL11_4: L11.4 U13.7 | length 6.9
  Top w0.132: U13.7@30,53.7 30,53.084 29.934,53.018 29.934,52.875 30.4,52.41 32.35,52.41 32.365,52.425 33.225,52.425 33.593,52.057 33.593,51.532 33.103,51.041 32.816,51.041 32.6,50.825 L11.4@32.325,50.825
NetL12_1: L12.1 U13.8 | length 46.4
  Top w0.132: U13.8@30.5,53.7 30.5,53.175 30.775,52.9 32.2,52.9 32.175,52.875 32.177,52.873 v1(32.177,52.828)
  Signal_3 w0.157: v1(14.325,27.2) 14.184,27.059 14.184,24.816 14.8,24.2 16.131,24.2 16.342,23.989 16.698,23.989 16.951,24.242 16.951,24.422 17.9,25.371 17.9,26.25 20.407,28.757 20.407,29.528 24.7,33.821 24.7,35.421 27.4,38.121 27.4,39.221 29.5,41.321 29.5,43.2 29.032,43.668 29.032,45.353 30.6,46.921 30.6,48.752 31.673,49.825 32.375,49.825 32.556,50.006 32.556,50.175 32.556,50.229 ccw(c32.418,50.229) 32.418,50.366 32.212,50.366 cw(c32.212,50.504) 32.075,50.504 32.075,50.687 cw(c32.212,50.687) 32.212,50.824 32.418,50.824 ccw(c32.418,50.961) 32.556,50.961 32.556,51.144 ccw(c32.418,51.144) 32.418,51.281 32.212,51.281 cw(c32.212,51.419) 32.075,51.419 32.075,51.602 cw(c32.212,51.602) 32.212,51.739 32.418,51.739 ccw(c32.418,51.876) 32.556,51.876 32.556,52.196 32.556,52.425 32.556,52.603 32.34,52.819 32.181,52.819 32.177,52.823 v1(32.177,52.828)
  Bottom w0.132: L12.1@14.325,26.427 v1(14.325,27.2)
NetL12_4: L12.4 U13.9 | length 46.7
  Top w0.132: U13.9@31,53.7 31,53.475 31.2,53.275 31.775,53.275 31.982,53.482 32.253,53.482 32.271,53.5 32.6,53.5 32.65,53.45 v1(32.65,53.175)
  Signal_3 w0.157: v1(13.476,27.276) 13.599,27.276 13.816,27.059 13.816,24.663 14.647,23.832 15.978,23.832 16.189,23.621 16.851,23.621 17.319,24.089 17.319,24.269 18.268,25.218 18.268,26.097 20.775,28.604 20.775,29.375 25.068,33.668 25.068,35.278 25.423,35.632 25.432,35.632 27.768,37.968 27.768,39.068 29.868,41.168 29.868,43.353 29.4,43.821 29.4,45.2 30.968,46.768 30.968,48.603 31.848,49.483 32.205,49.483 32.231,49.457 32.528,49.457 32.924,49.853 32.924,52.756 32.706,52.974 32.706,53.119 v1(32.65,53.175)
  Bottom w0.132: v1@13.501,27.276 13.525,27.253 L12.4@13.525,26.427
NetNT1_1: NT1.1 U20.34 | length 0.7
  Bottom w0.127: NT1.1@34.452,47 U20.34@35.17,47
NetQ1_D: Q1.D R23.2 | length 1.4
  Bottom w0.127: R23.2@81.08,20.9 81.08,20.875 81.755,20.2 Q1.D@82.21,20.2
NetQ4_D: Q4.D R152.1 | length 1.2
  Bottom w0.127: R152.1@70.2,22.905 70.318,22.787 70.675,22.787 70.675,22.775 70.85,22.6 Q4.D@71.31,22.6
NetQ7_1: Q7.1 R20.2 | length 1.3
  Bottom w0.3: Q7.1@83.95,15.47 83.95,14.23 R20.2@84,14.18
NetQ9_D: Q9.D R166.1 | length 3.8
  Bottom w0.3: Q9.D@37.65,34.1 37.65,35.55 38.5,36.4 R166.1@38.5,37.52
NetQ10_D: Q10.D R167.1 | length 1.6
  Bottom w0.127: R167.1@39.6,61.38 39.625,61.38 40.188,61.943 40.188,62.138 40.45,62.4 Q10.D@40.65,62.4
NetQ11_D: Q11.D R160.1 | length 2.8
  Bottom w0.127: R160.1@34.395,23.25 34.395,24.995 35.025,25.625 Q11.D@35.225,25.625
NetQ12_D: Q12.D R161.1 | length 2
  Top w0.127: R161.1@34,60.08 34.068,60.012 35.6,60.012 Q12.D@35.6,60.35
NetR4_1: R4.1 R7.1 R8.1 R9.1 R231.2 R256.1 R257.2 | length 15.9
  Signal_7 w0.4: v1(52.38,57.62) 53,58.24 53,59.425 53.9,60.325 57.375,60.325 v1(58,59.7) v1(59.2,59.7)
  Bottom w0.2: R8.1@55.93,38 v1(56.63,37.3)
  Bottom w0.3: R9.1@57.08,32.4 57.155,32.325 v1(57.65,32.325) ; v1(69.9,59.72) 69.905,59.715 R4.1@69.905,58.9 ; R231.2@74.92,58.3 74.95,58.33 v1(74.95,59) ; v1(80,38.6) 80,38.78 R7.1@80.62,39.4
  Bottom w0.4: R256.1@52.055,56.7 52.055,57.295 v1(52.38,57.62) ; v1(59.2,59.7) 59.22,59.72 59.22,60.625 R257.2@59.845,61.25
NetR4_2: R4.2 U1.U1 | length 1.7
  Top w0.127: v1(68.2,59) 68.2,58.83 U1.U1@68.75,58.28
  Bottom w0.127: v1(68.2,59) 68.845,59 R4.2@68.945,58.9
NetR5_2: R5.2 U1.D15 | length 5.6
  Top w0.127: U1.D15@85.26,40.5 85.929,39.831 v1(85.929,39.827)
  Bottom w0.127: R5.2@81.58,40.5 81.784,40.296 85.455,40.296 85.923,39.827 v1(85.929,39.827)
NetR6_2: R6.2 U1.E14 | length 4.6
  Top w0.127: U1.E14@83.99,41.77 84.6,42.38 v1(84.61,42.38)
  Bottom w0.127: R6.2@81.58,41.5 81.726,41.354 81.821,41.354 82.125,41.05 83.28,41.05 v1(84.61,42.38)
NetR7_2: R7.2 U1.E16 | length 4.2
  Top w0.127: U1.E16@83.99,39.23 84.6,38.62 v1(84.6,38.61)
  Bottom w0.127: R7.2@81.58,39.4 81.826,39.154 84.057,39.154 v1(84.6,38.61)
NetR8_2: R8.2 U1.AG17 | length 1.9
  Top w0.127: v1(55.4,38.525) 55.725,38.525 56.05,38.2 U1.AG17@56.05,37.96
  Bottom w0.127: R8.2@54.97,38 54.97,38.32 55.113,38.463 55.338,38.463 v1(55.4,38.525)
NetR9_2: R9.2 U1.AG22 | length 2.6
  Top w0.127: v1(55.43,31) 55.44,31 U1.AG22@56.05,31.61
  Bottom w0.127: v1(55.43,31) 55.899,31.469 55.899,32.179 R9.2@56.12,32.4
NetR11_2: R11.2 R59.2 U6.8 | length 3.5
  Top w0.127: U6.8@18.62,28.295 U6.8@18.53,28.385 18.1,28.385 R11.2@18.1,27.04 R59.2@19.74,27.04
NetR26_1: R26.1 R27.2 U27.4 | length 3.9
  Bottom w0.3: R26.1@43,33.25 43.1,33.35 R27.2@44.75,33.35 44.75,33.75 43.75,34.75 U27.4@43.75,35.02
NetR34_1: R34.1 S2.4 | length 2.1
  Top w0.127: R34.1@31.68,20.2 31.69,20.21 S2.4@31.69,22.265
NetR35_1: R35.1 S2.3 | length 2.3
  Top w0.127: R35.1@29.7,22.78 30.28,22.78 31.035,23.535 S2.3@31.69,23.535
NetR43_1: R43.1 R44.2 U3.4 | length 2.9
  Bottom w0.2: U3.4@50.5,62.4 51.25,62.4 51.45,62.2 R43.1@52.27,62.2
  Bottom w0.25: R43.1@52.27,62.2 R43.1@52.3,62.17
  Bottom w0.3: R44.2@52.3,61.18 R43.1@52.3,62.17
NetR45_2: R45.2 R47.1 U3.9 | length 5.5
  Bottom w0.2: 48.348,62.798 48.45,62.9 U3.9@48.9,62.9
  Bottom w0.25: R45.2@44.4,63.495 R47.1@44.4,62.58 45.18,62.58 45.398,62.798 48.348,62.798
NetR46_2: R46.2 U3.5 | length 2
  Bottom w0.25: R46.2@50.4,59.98 50.5,60.08 U3.5@50.5,61.9
NetR49_1: R49.1 R50.2 U3.7 | length 3.2
  Bottom w0.2: R50.2@47.8,61 48.7,61.9 U3.7@48.9,61.9
  Bottom w0.25: R49.1@46.1,61 R50.2@47.6,61 R50.2@47.8,61
NetR61_2: R61.2 R233.2 U7.8 | length 48
  Signal_4 w0.142: v1(11.84,46.22) 14.57,46.22 16.073,47.723 20.775,47.723 20.827,47.671 20.946,47.671 v1(21.025,47.75) ; v1(15.475,20.125) 15.847,19.753 18.44,19.753 20.05,21.363 v1(20.05,22.95)
  Signal_7 w0.142: v1(20.05,22.95) 20.05,27.025 18.9,28.175 18.9,31.65 19.4,32.15 19.4,35.45 18.05,36.8 18.05,39.479 20.071,41.5 20.071,45.446 21.025,46.4 v1(21.025,47.75)
  Bottom w0.127: v1(11.84,46.22) 11.859,46.201 R61.2@12.459,46.201 12.464,46.196 U7.8@14.389,46.196 ; v1(15.475,20.125) 16.295,19.305 R233.2@16.295,19.125
NetR65_2: R65.2 U10.5 | length 2.3
  Bottom w0.127: R65.2@13.075,34.47 13.18,34.47 13.825,33.825 13.825,32.6 U10.5@13.775,32.55
NetR66_2: R66.2 U10.4 | length 2
  Bottom w0.127: R66.2@13.205,33.5 13.052,33.347 13.052,32.423 13.325,32.15 U10.4@13.775,32.15
NetR75_1: R75.1 U11.40 | length 1.6
  Bottom w0.127: U11.40@24.54,33.142 24.576,33.179 24.576,33.689 24.616,33.728 24.616,34.636 R75.1@24.54,34.712
NetR81_2: R81.2 U11.41 | length 3.2
  Bottom w0.2: U11.41@24.94,33.142 24.94,34.196 25.125,34.381 25.125,35.7 25.27,35.845 R81.2@25.675,35.845
NetR82_2: R82.2 U11.9 | length 3.9
  Bottom w0.127: U11.9@28.49,29.192 29.179,29.192 30.1,28.271 30.1,27.281 30.534,26.846 30.574,26.846 R82.2@30.795,26.625
NetR107_1: R107.1 U12.40 | length 1.4
  Top w0.127: R107.1@24.78,43.875 24.855,43.8 U12.40@26.15,43.8
NetR110_1: R110.1 U28.11 | length 1.3
  Top w0.15: R110.1@95.305,45.2 96.08,45.975 U28.11@96.275,45.975
NetR111_1: R111.1 U28.10 | length 1.1
  Top w0.15: R111.1@95.305,46.225 95.734,46.225 95.984,46.475 U28.10@96.275,46.475
NetR113_2: R113.2 U12.41 | length 5.4
  Top w0.127: v1(24.25,41.825) 24.25,42.675 24.485,42.91 24.672,42.91 25.188,43.425 26.125,43.425 U12.41@26.15,43.4
  Bottom w0.127: R113.2@22.57,40.95 R113.2@22.57,41.05 22.57,41.395 22.725,41.55 23.937,41.55 24.211,41.825 v1(24.25,41.825)
NetR114_2: R114.2 U12.9 | length 5.2
  Top w0.127: U12.9@30.1,39.85 30.1,38.6 30.825,37.875 33.72,37.875 R114.2@33.745,37.85
NetR136_1: R136.1 U13.28 | length 3.9
  Top w0.127: R136.1@24.945,61.925 24.945,60.28 26.2,59.025 U13.28@26.2,58.5
NetR138_2: R138.2 U13.22 | length 2.2
  Top w0.127: U13.22@29.5,59.3 29.5,59.95 29.853,60.303 v1(30.026,60.303)
  Bottom w0.127: R138.2@30.025,59.53 30.1,59.605 30.025,59.68 30.026,59.681 v1(30.026,60.303)
NetR139_2: R139.2 U13.24 | length 2
  Top w0.127: U13.24@28.5,59.3 28.5,60.202 v1(28.601,60.303)
  Bottom w0.127: v1(28.601,60.303) 28.601,60.189 28.6,60.188 28.704,60.084 28.704,59.751 28.925,59.53 R139.2@28.95,59.53
NetR140_2: R140.2 U13.25 | length 1.8
  Top w0.127: U13.25@28,59.3 v1(28,60.3)
  Bottom w0.127: R140.2@28,59.53 v1(28,60.3)
NetR141_2: R141.2 U13.35 | length 3.2
  Top w0.127: R141.2@23.5,53.68 23.916,54.096 24.594,54.096 25.46,54.961 26.161,54.961 U13.35@26.2,55
NetR150_2: R150.2 R151.2 U19.A3 | length 3
  Bottom w0.127: R150.2@69.23,21.375 69.451,21.154 69.451,20.799 70.18,20.07 70.18,20.045 70.88,19.345 U19.A3@70.88,19.05
NetR151_1: R151.1 R152.2 | length 0.9
  Bottom w0.127: R152.2@70.2,21.945 70.2,21.035 R151.1@70.205,21.03
NetR155_2: R155.2 U20.2 | length 1.7
  Bottom w0.127: U20.2@42.03,49.8 43.12,49.8 R155.2@43.52,50.2
NetR156_2: R156.2 U20.4 | length 1.6
  Bottom w0.127: U20.4@42.03,49 42.046,49.016 43.261,49.016 43.52,49.275 R156.2@43.52,49.3
NetR157_2: R157.2 U20.54 | length 1.6
  Bottom w0.127: U20.54@40.4,51.03 40.436,51.066 40.436,51.557 41.175,52.295 R157.2@41.2,52.295
NetR158_2: R158.2 U20.1 | length 1.9
  Bottom w0.127: U20.1@42.03,50.2 42.36,50.2 43.064,50.903 43.299,50.903 43.52,51.125 R158.2@43.52,51.15
NetR205_2: R205.2 U1.AH7 | length 1.6
  Top w0.127: v1(54.17,51.28) 54.17,51.27 U1.AH7@54.78,50.66
  Bottom w0.127: R205.2@53.48,51.3 53.5,51.28 v1(54.17,51.28)
NetR219_2: R219.2 U1.AL6 U1.AL7 U1.AL8 | length 3.7
  Top w0.3: v1(50.35,49.375) v1(50.35,49.95) 50.97,49.95 ; U1.AL8@50.97,49.39 50.97,49.95 ; U1.AL6@50.97,51.93 U1.AL7@50.97,50.66 50.97,49.95
NetR220_2: R220.2 U1.AJ2 U1.AJ3 U1.AJ4 U1.AK2 U1.AK3 U1.AK4 | length 11.5
  Top w0.3: U1.AK3@52.24,55.74 U1.AK4@52.24,54.47 U1.AJ4@53.51,54.47 U1.AJ3@53.51,55.74 ; U1.AK3@52.24,55.74 U1.AK2@52.24,57.01 U1.AJ2@53.51,57.01 53.51,56.625 ; U1.AK3@52.24,55.74 U1.AJ3@53.51,55.74 ; U1.AJ3@53.51,55.74 53.51,56.1 ; 53.51,56.1 53.51,56.363 ; 53.51,56.1 v1(54.2,56.1) 54.2,56.35 ; 53.51,56.363 54.187,56.363 54.2,56.35 ; 53.51,56.363 53.51,56.625 ; 53.51,56.625 v1(54.2,56.625) 54.2,56.35
  Bottom w0.2: v1(54.2,56.625) v1@54.225,56.625
NetR221_2: R221.2 R230.1 U1.AJ10 | length 31.1
  Top w0.2: v1(52.9,47.47) 53.51,46.86 U1.AJ10@53.51,46.85
  Bottom w0.2: R221.2@52.9,46.73 v1(52.9,47.47) 53.464,48.034 56.507,48.034 56.541,48 56.915,48 57.18,48.265 57.18,48.521 57.82,49.161 57.82,57.194 58.477,57.851 72.551,57.851 R230.1@73,58.3
NetR222_2: R222.2 U1.G4 | length 1.6
  Top w0.15: U1.G4@81.45,54.47 82.06,53.86 v1(82.06,53.85)
  Bottom w0.15: v1(82.06,53.85) R222.2@82.788,53.85
NetR223_2: R223.2 U1.G3 | length 1.7
  Top w0.15: U1.G3@81.45,55.74 82.05,55.14 v1(82.02,55.14)
  Bottom w0.15: v1(82.02,55.14) 82.04,55.14 82.28,54.9 R223.2@82.775,54.9
NetR224_2: R224.2 U1.G10 | length 2.3
  Top w0.15: U1.G10@81.45,46.85 82.06,46.24 v1(82.06,46.22)
  Bottom w0.15: v1(82.06,46.22) 82.06,46.23 82.9,47.07 R224.2@82.9,47.27
NetR225_2: R225.2 U1.G9 | length 2.3
  Top w0.15: v1(80.83,47.51) 80.84,47.51 U1.G9@81.45,48.12
  Bottom w0.15: v1(80.83,47.51) 80.83,47.12 80.925,47.025 81.455,47.025 R225.2@81.7,47.27
NetR226_2: R226.2 U1.G7 | length 1.6
  Top w0.15: v1(80.84,51.28) 80.84,51.27 U1.G7@81.45,50.66
  Bottom w0.15: v1(80.84,51.28) 80.85,51.29 R226.2@80.85,52.02
NetR227_2: R227.2 U1.G6 | length 1.6
  Top w0.15: U1.G6@81.45,51.93 82.06,51.32 v1(82.08,51.32)
  Bottom w0.15: R227.2@82.05,52.02 82.05,51.32 v1(82.08,51.32)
